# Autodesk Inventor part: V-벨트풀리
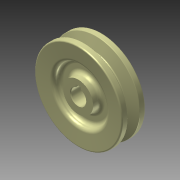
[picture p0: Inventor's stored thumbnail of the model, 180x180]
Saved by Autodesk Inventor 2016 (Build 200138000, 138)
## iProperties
Created: 2016-08
Part Number: V-벨트풀리
Material: 일반
Document SubType Name: Modeling
Designer: mduedu
Density: 1 g/cm^3
Mass: 44.0848 g
Surface Area: 158.218 cm^2
Volume: 44.0848 cm^3
Appearance: 알루미늄 - 평지
Author: mduedu
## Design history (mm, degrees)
sketch "스케치1"
  geometry: L1 (0, 9.5)-(0, -9.5); L2 (0, 9.5)-(35, 9.5); L3 (35, 9.5)-(35, 4.825); L4 (35, 4.825)-(26, 2.074); L5 (26, 2.074)-(26, 0); L6 (0, 0)-(26, 0); L7 (0, -9.5)-(35, -9.5); L8 (35, -9.5)-(35, -4.825); L9 (35, -4.825)-(26, -2.074); L10 (26, -2.074)-(26, 0); L11 (32.3, 9.5)-(32.3, -9.5); 3 further points
  constraints: 22 end point, 6 point on line, 4 perpendicular, 3 symmetric about line, 1 coincident, 1 horizontal alignment, 1 midpoint, 1 parallel, 1 vertical
  dimensions: "d0" = 19 distance of L1.start L1.end; "d2" = 70 diameter of L8 L1; "d4" = 6.3 distance between parallel lines of L10 L11; "d5" = 2.7 distance between parallel lines of L11 L8; "d6" = 8 distance of point (32.3, -4) point (32.3, 4); "d7" = 34 deg angle of L9 L4
revolve "회전1" sketch "스케치1" stored, may be unused: angle "d8" = 90 deg
sketch "스케치2"
  geometry: L1 (-2, 0)-(2, 0); L2 (2, 0)-(2, 7.8); L3 (2, 7.8)-(-2, 7.8); L4 (-2, 7.8)-(-2, 0); C1 r 6 at (0, 0); 2 further points
  constraints: 8 end point, 2 coincident, 2 parallel, 1 centre point, 1 horizontal, 1 midpoint, 1 perpendicular
  dimensions: "d9" = 12 diameter of C1; "d11" = 4 distance of L2.end L3.end; "d12" = 7.8 distance of L1.end L2.end
extrude "돌출1" cut sketch "스케치2" stored distance "d13" = 10; taper "d14" = 0 deg
sketch "스케치3"
  geometry: L1 (35, 4.825)-(26, 2.074) reference; L2 (26, 2.074)-(26, -2.074) reference; L3 (0, 0)-(26, 0); L4 (35, 9.5)-(35, 4.825) reference; L5 (-35, 9.5)-(35, 9.5) reference; L6 (35, 9.5)-(21, 8.275); L7 (21, 8.275)-(21, 3); L8 (21, 3)-(12, 3); L9 (12, 3)-(12, 9.5); L10 (0, 9.5)-(0, -9.5); L11 (5.657, -9.5)-(-6, -9.5) reference; L12 (12, 9.5)-(35, 9.5)
  constraints: 14 end point, 3 midpoint, 2 perpendicular, 2 point on line, 1 collinear, 1 horizontal, 1 parallel
  dimensions: "d15" = 3 distance between parallel lines of L3 L8; "d17" = 42 diameter of L7 L10; "d18" = 24 diameter of L9 L10; "d31" = 5 deg angle of L6 L5
revolve "회전2" sketch "스케치3" stored, may be unused: angle "d19" = 90 deg
fillet "모깎기1" dims "d20" = 0.5, "d21" = 1, "d22" = 1
fillet "모깎기2" dims "d23" = 3
fillet "모깎기3" dims "d24" = 3
fillet "모깎기4" dims "d25" = 3
chamfer "모따기1" distance "d26" = 0.5; stored, may be unused: second distance "d27" = 2, angle "d28" = 45 deg
node "솔리드1"
mirror "대칭1"
